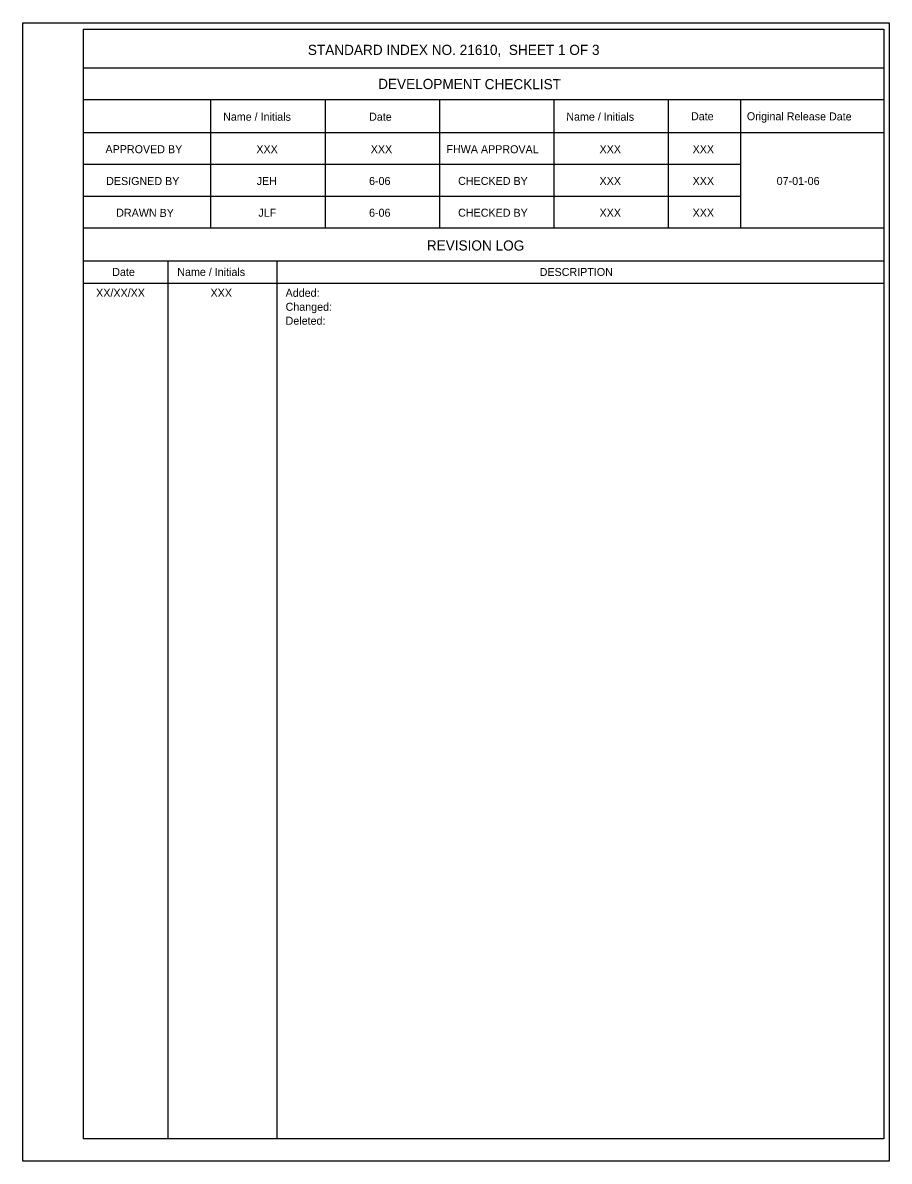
# Model space of a CAD drawing. Extents: x 115718.2 to 115735.9, y 111778.8 to 111787.4.
# Drawn here: x 115730.4 to 115735.85, y 111780.26 to 111787.43 of the extents above; entities that cross this region are included whole.
import ezdxf

# ---------------------------------------------------------------- set-up
doc = ezdxf.new("R2010")
doc.units = 0
for name, color, linetype in [('Border', 7, 'Continuous'), ('PlotBorder_dp', 7, 'Continuous'), ('TextStructures', 7, 'Continuous')]:
    doc.layers.add(name, color=color, linetype=linetype)

msp = doc.modelspace()

# ---------------------------------------------------------------- linework, layer by layer
at = {"layer": 'Border'}
for p, q in [((115735.821, 111787.1406), (115730.7842, 111787.1406)), ((115735.821, 111786.9406), (115730.7842, 111786.9406)), ((115731.5842, 111786.9406), (115731.5842, 111786.1336)), ((115732.3042, 111786.9406), (115732.3042, 111786.1336)), ((115733.0242, 111786.9406), (115733.0242, 111786.1336)), ((115733.7442, 111786.9406), (115733.7442, 111786.1336)), ((115734.4642, 111786.9406), (115734.4642, 111786.1336)), ((115734.918, 111786.9406), (115734.918, 111786.1336)), ((115735.821, 111786.7336), (115730.7842, 111786.7336)), ((115734.918, 111786.5336), (115730.7842, 111786.5336)), ((115734.918, 111786.3336), (115730.7842, 111786.3336)), ((115735.821, 111786.1336), (115730.7842, 111786.1336)), ((115735.821, 111785.9266), (115730.7842, 111785.9266)), ((115731.3143, 111785.9266), (115731.3143, 111780.4)), ((115731.9999, 111785.9266), (115731.9999, 111780.4)), ((115735.821, 111785.7857), (115730.7842, 111785.7857))]:
    msp.add_line(p, q, dxfattribs=at)
msp.add_lwpolyline([(115730.7843, 111787.3857), (115735.821, 111787.3857), (115735.821, 111780.4), (115730.7843, 111780.4)], close=True, dxfattribs=at)
at = {"layer": 'PlotBorder_dp'}
msp.add_line((115730.4016, 111780.2597), (115730.4016, 111780.2597), dxfattribs=at)
msp.add_lwpolyline([(115730.4016, 111787.4264), (115735.855, 111787.4264), (115735.855, 111780.2597), (115730.4016, 111780.2597)], close=True, dxfattribs=at)

# ---------------------------------------------------------------- texts
at = {"layer": 'TextStructures'}
for s, height, p in [('STANDARD INDEX NO. 21610,  SHEET 1 OF 3', 0.064, (115732.1957, 111787.2237)), ('XXX', 0.0504, (115731.8718, 111786.6053)), ('XXX', 0.0504, (115732.5918, 111786.6053)), ('XXX', 0.0504, (115734.0318, 111786.6053)), ('XXX', 0.0504, (115734.6176, 111786.6053)), ('JEH', 0.0504, (115731.8736, 111786.4053)), ('6-06', 0.0504, (115732.581, 111786.4053)), ('XXX', 0.0504, (115734.0318, 111786.4053)), ('XXX', 0.0504, (115734.6176, 111786.4053)), ('07-01-06', 0.0504, (115735.1466, 111786.4053)), ('JLF', 0.0504, (115731.8842, 111786.2053)), ('6-06', 0.0504, (115732.581, 111786.2053)), ('XXX', 0.0504, (115734.0318, 111786.2053)), ('XXX', 0.0504, (115734.6176, 111786.2053)), ('DESCRIPTION', 0.0504, (115733.6551, 111785.8324)), ('XX/XX/XX', 0.0504, (115730.8632, 111785.7012)), ('XXX', 0.0504, (115731.5834, 111785.7012)), ('Added:', 0.0504, (115732.0558, 111785.7012)), ('Changed:', 0.0504, (115732.0558, 111785.6133)), ('Deleted:', 0.0504, (115732.0558, 111785.5254))]:
    msp.add_text(s, height=height, dxfattribs=at).set_placement(p)
for s, height, p in [('DEVELOPMENT CHECKLIST', 0.064, (115732.6382, 111787.0098)), ('Name / Initials', 0.0504, (115731.6624, 111786.8103)), ('Date', 0.0504, (115732.5811, 111786.8099)), ('Name / Initials', 0.0504, (115733.8224, 111786.8103)), ('Date', 0.0504, (115734.6073, 111786.8128)), ('Original Release Date', 0.0504, (115734.9589, 111786.8128)), ('APPROVED BY', 0.0504, (115730.9222, 111786.6058)), ('FHWA APPROVAL', 0.0504, (115733.068, 111786.6058)), ('DESIGNED BY', 0.0504, (115730.9264, 111786.4054)), ('CHECKED BY', 0.0504, (115733.1417, 111786.4058)), ('DRAWN BY', 0.0504, (115730.9896, 111786.2053)), ('CHECKED BY', 0.0504, (115733.1417, 111786.2058)), ('REVISION LOG', 0.064, (115732.9445, 111785.9933)), ('Date', 0.0504, (115730.9648, 111785.8326)), ('Name / Initials', 0.0504, (115731.374, 111785.833))]:
    msp.add_text(s, height=height, rotation=359.87563, dxfattribs=at).set_placement(p)

doc.saveas('drawing.dxf')
